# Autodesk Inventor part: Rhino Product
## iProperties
Created: 2005-05
Part Number: Rhino Product
Cost Center: 0.02 kg
Document SubType Name: Modeling
Designer: W. Holzwarth
Authority: 19853 mm^3
Übersetzungsnorm: STEP AP214DIS
Dateiname: Dozer_aus_Rhino
Postprozessor: Build: 211m, Release: 10 - Date: Fri 03/18/2005
Gesendete Einheiten: MILLIMETERS
Unbestimmtheit: 0.01
SaveDate: 2005-05-30
SaveTime: 15:24
TotalMass: 0.02 kg
TotalVolume: 19853 mm^3
Author: W. Holzwarth
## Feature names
1. Basis1
2. Extrusion1
